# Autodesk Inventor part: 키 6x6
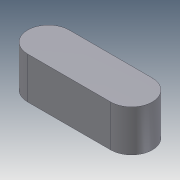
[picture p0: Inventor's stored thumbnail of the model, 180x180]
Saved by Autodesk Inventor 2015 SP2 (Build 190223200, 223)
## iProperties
Company: 한국ATC센터
Created: 2013-01
Part Number: 키 6x6
Document SubType Name: Modeling
Designer: KYOUNG IL JANG
Density: 7.15 g/cm^3
Material: 주철
Mass: 4.30177 g
Surface Area: 4.57646 cm^2
Volume: 0.601646 cm^3
Appearance: 강철
Author: KYOUNG IL JANG
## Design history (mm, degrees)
sketch "스케치1"
  geometry: L1 (-6, -3)-(6, -3); L2 (6, 3)-(-6, 3); A1 r 3 centre (6, 0) between (6, -3) and (6, 3); A2 r 3 centre (-6, 0) between (-6, 3) and (-6, -3); 2 further points
  constraints: 4 end point, 4 point on circle, 4 tangent, 2 centre point, 1 horizontal, 1 horizontal alignment, 1 midpoint, 1 parallel, 1 vertical alignment
  dimensions: "d0" = 18 dimension on A1 A2; "d1" = 6 distance between parallel lines of L1 L2
extrude "돌출1" new body sketch "스케치1" stored distance "d2" = 6; taper "d3" = 0 deg
node "솔리드1"
